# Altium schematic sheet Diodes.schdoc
size 91 x 65 mm
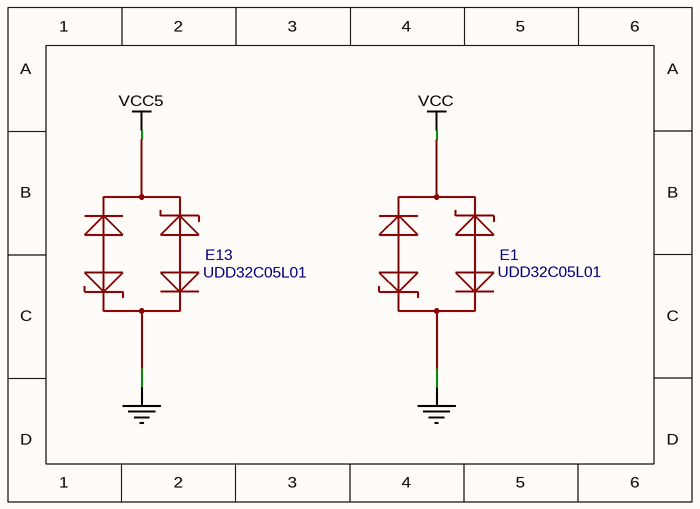
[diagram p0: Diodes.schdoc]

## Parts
E1  UDD32C05L01  [SOD-323-BI]
E13  UDD32C05L01  [SOD-323-BI]

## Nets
GND: E1.2 E13.1
VCC: E1.1
VCC5: E13.2

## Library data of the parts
E1 = UDD32C05L01: BOM_Manufacturer: Brightking; BOM_Manufacturer Part: UDD32C03L01; SMT Type: Extend
E13 = UDD32C05L01: BOM_Manufacturer: Brightking; SMT Type: Extend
